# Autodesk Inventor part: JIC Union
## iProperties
Category: Hydraulics
Title: JIC Union
Author: QBZ
Shininess: 27.0
PropertySet Name: _Private Model Information
Created: 2001-03
Part Number: 2027-6-6S
Material: Steel, Mild
Catalog Web Link: http://www.aeroquip.com
Description: FTX Male Connector 6-6
Document SubType Name: Modeling
Designer: QBZ
Control State: 0
Master: False
Checked Out: False
PropertySet Name: Design Tracking Control
Density: 7.86
Volumn: 7.3241227782804
Area: 41.16363820292827
PropertySet Name: Model Information
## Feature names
1. Revolution1
2. Hole1
3. Revolution2
4. Hole5
